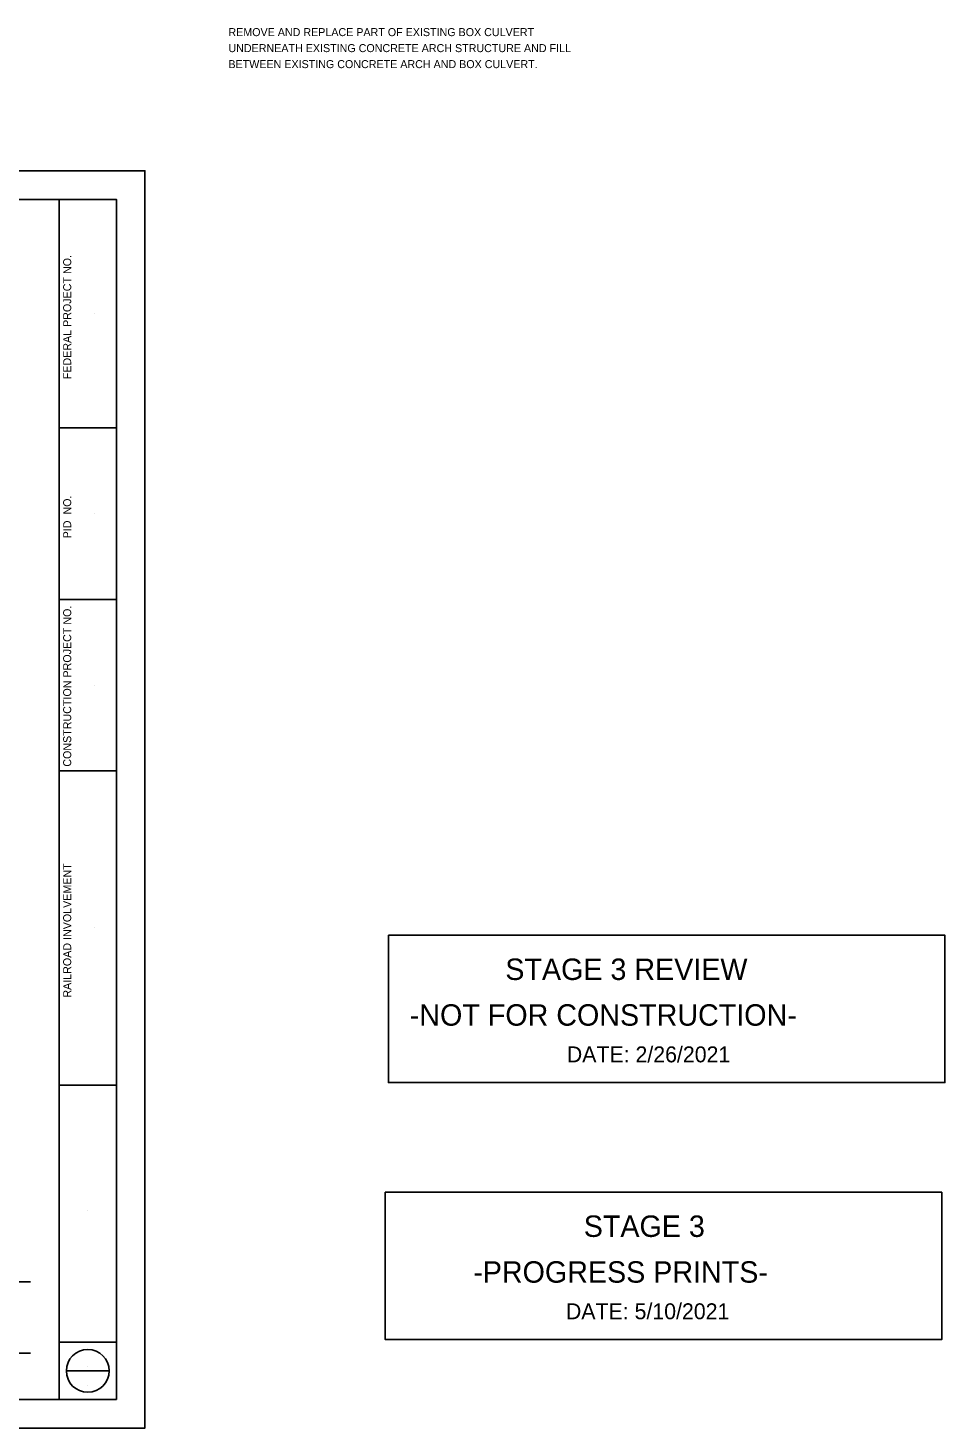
# Model space of a CAD drawing. Extents: x 421.3 to 469.3, y 221.6 to 248.2.
# Drawn here: x 453.26 to 469.3, y 221.63 to 246.13 of the extents above; entities that cross this region are included whole.
import ezdxf

# ---------------------------------------------------------------- set-up
doc = ezdxf.new("R2010")
doc.units = 0
for name, color, linetype in [('SH_Border', 7, 'Continuous'), ('SH_Cut_Line', 7, 'Continuous'), ('SH_Data', 7, 'Continuous'), ('SH_Text', 7, 'Continuous')]:
    doc.layers.add(name, color=color, linetype=linetype)

msp = doc.modelspace()

# ---------------------------------------------------------------- linework, layer by layer
at = {"layer": 'SH_Border'}
for p, q in [((453.808, 222.128), (453.808, 243.128)), ((453.808, 239.128), (454.808, 239.128)), ((453.808, 236.128), (454.808, 236.128)), ((453.808, 233.128), (454.808, 233.128)), ((453.808, 227.628), (454.808, 227.628)), ((453.808, 223.128), (454.808, 223.128))]:
    msp.add_line(p, q, dxfattribs=at)
msp.add_lwpolyline([(423.308, 243.128), (454.808, 243.128), (454.808, 222.128), (423.308, 222.128)], close=True, dxfattribs=at)
at = {"layer": 'SH_Cut_Line'}
msp.add_lwpolyline([(421.308, 221.628), (455.308, 221.628), (455.308, 243.628), (421.308, 243.628)], close=True, dxfattribs=at)
at = {"layer": 'SH_Data'}
for p, q in [((454.433, 241.128), (454.433, 241.128)), ((454.433, 237.628), (454.433, 237.628)), ((454.433, 234.628), (454.433, 234.628)), ((454.433, 230.394), (454.433, 230.394)), ((454.308, 225.428), (454.308, 225.428)), ((448.402, 224.188), (453.308, 224.188)), ((448.388, 222.94), (453.308, 222.94)), ((454.308, 222.713), (454.308, 222.713)), ((453.933, 222.628), (454.683, 222.628)), ((454.308, 222.373), (454.308, 222.373))]:
    msp.add_line(p, q, dxfattribs=at)
msp.add_circle((454.308, 222.628), 0.375, dxfattribs=at)
at = {"layer": 'SH_Text'}
for points in [[(459.567, 230.251), (469.301, 230.251), (469.301, 227.673), (459.567, 227.673)], [(459.511, 225.754), (469.246, 225.754), (469.246, 223.176), (459.511, 223.176)]]:
    msp.add_lwpolyline(points, close=True, dxfattribs=at)

# ---------------------------------------------------------------- texts
at = {"layer": 'SH_Data'}
for s, height, p in [('REMOVE AND REPLACE PART OF EXISTING BOX CULVERT         ', 0.14, (456.768, 245.984)), ('UNDERNEATH EXISTING CONCRETE ARCH STRUCTURE AND FILL    ', 0.14, (456.768, 245.704)), ('BETWEEN EXISTING CONCRETE ARCH AND BOX CULVERT.         ', 0.14, (456.768, 245.424)), ('STAGE 3 REVIEW', 0.375, (461.611, 229.468)), ('-NOT FOR CONSTRUCTION-', 0.375, (459.94, 228.668)), ('DATE: 2/26/2021', 0.27869, (462.687, 228.027)), ('STAGE 3', 0.375, (462.983, 224.972)), ('-PROGRESS PRINTS-', 0.375, (461.05, 224.171)), ('DATE: 5/10/2021', 0.27869, (462.671, 223.531))]:
    msp.add_text(s, height=height, dxfattribs=at).set_placement(p)
for s, p in [('FEDERAL PROJECT NO.', (454.018, 239.98)), ('PID  NO.', (454.018, 237.196)), ('CONSTRUCTION PROJECT NO.', (454.018, 233.2)), ('RAILROAD INVOLVEMENT', (454.018, 229.159))]:
    msp.add_text(s, height=0.14, rotation=90, dxfattribs=at).set_placement(p)

doc.saveas('drawing.dxf')
